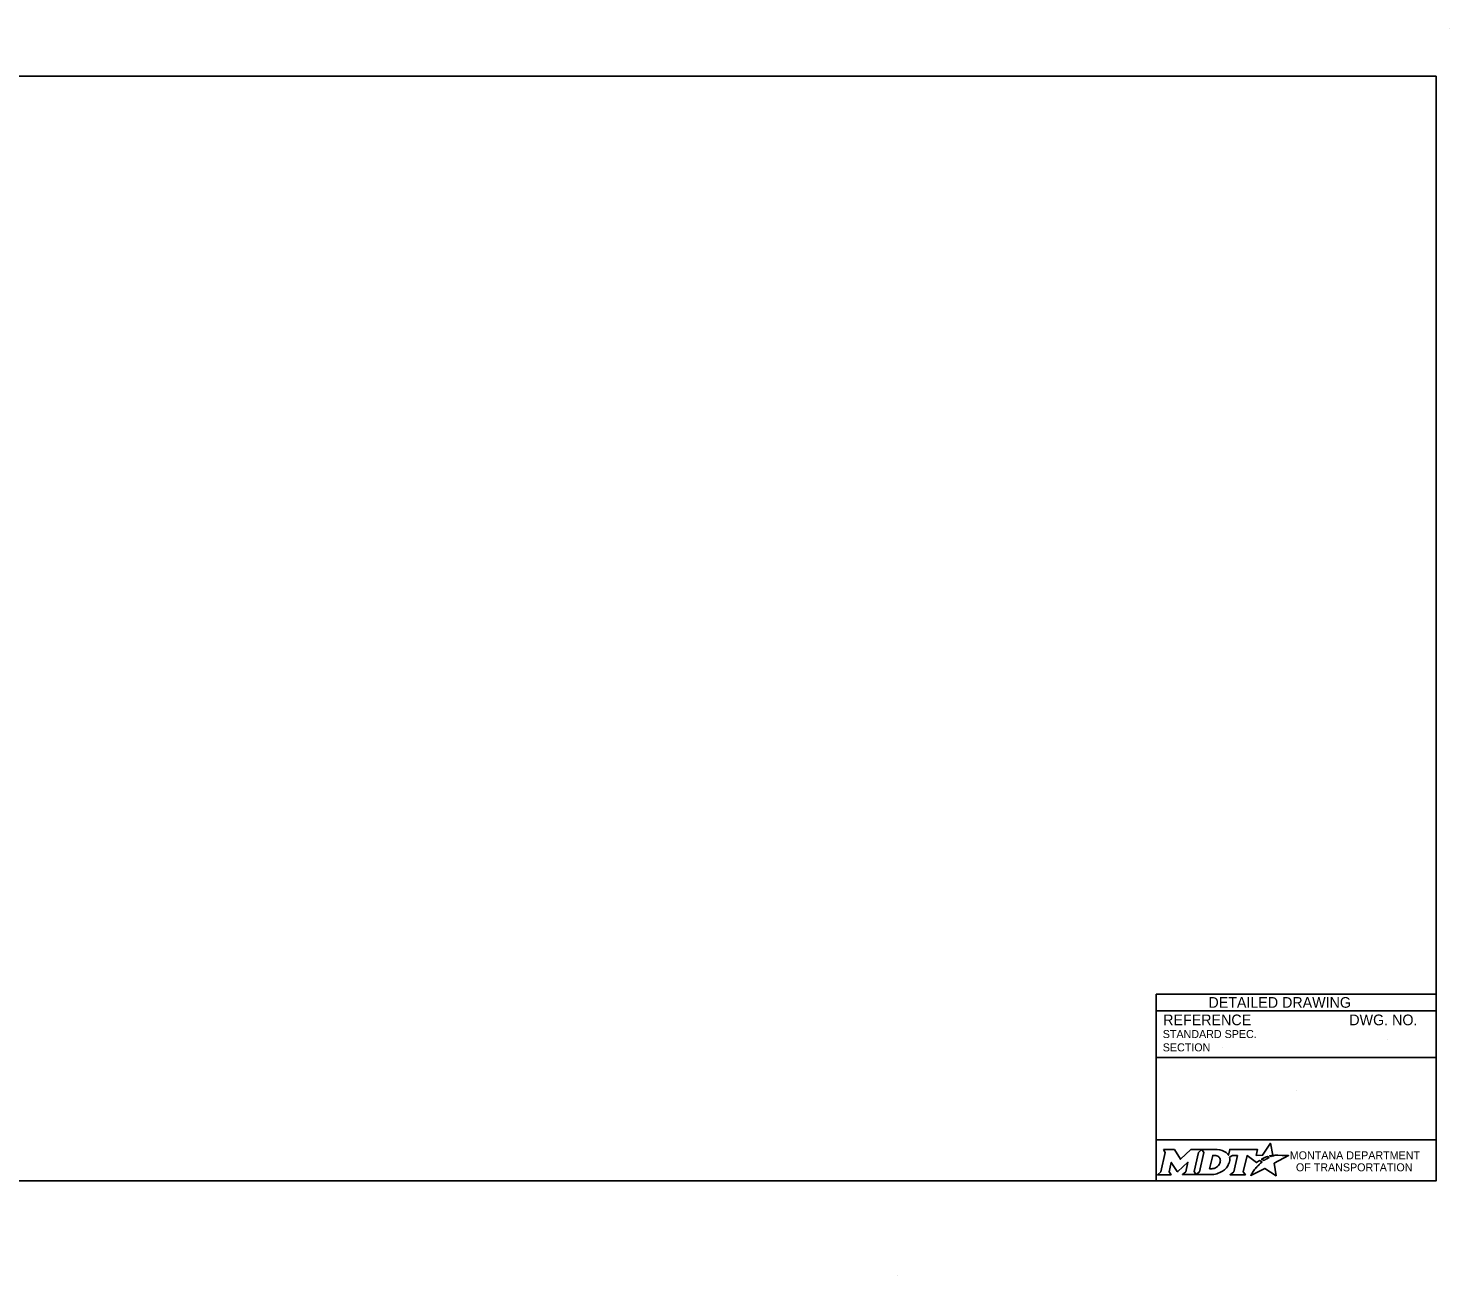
# Model space of a CAD drawing. Extents: x 49991.4 to 50021, y 49987.6 to 50011.4.
# Drawn here: x 50010.39 to 50021.04, y 49999.18 to 50008.52 of the extents above; entities that cross this region are included whole.
import ezdxf

# ---------------------------------------------------------------- set-up
doc = ezdxf.new("R2010")
doc.units = 0
for name, color, linetype in [('Default', 7, 'Continuous'), ('Level 1', 7, 'Continuous'), ('Level 4', 7, 'Continuous')]:
    doc.layers.add(name, color=color, linetype=linetype)

msp = doc.modelspace()

# ---------------------------------------------------------------- linework, layer by layer
at = {"layer": 'Default'}
for points in [[(50019.7, 50000.068), (50019.69, 50000.074), (50019.702, 50000.076), (50019.713, 50000.078), (50019.696, 50000.168), (50019.636, 50000.077), (50019.589, 50000.076), (50019.599, 50000.12), (50019.39, 50000.121), (50019.38, 50000.078), (50019.374, 50000.086)], [(50018.893, 50000.121), (50018.907, 50000.097), (50018.874, 49999.954), (50018.848, 49999.931), (50018.95, 49999.931), (50018.936, 49999.954), (50018.952, 50000.024), (50018.996, 49999.955), (50019.002, 49999.955), (50019.077, 50000.025), (50019.06, 49999.954), (50019.035, 49999.932), (50019.137, 49999.932), (50019.123, 49999.955), (50019.156, 50000.097)], [(50019.156, 50000.097), (50019.182, 50000.121), (50019.099, 50000.121), (50019.02, 50000.048), (50018.975, 50000.12), (50018.893, 50000.121)], [(50019.295, 50000.121), (50019.182, 50000.121), (50019.196, 50000.098), (50019.163, 49999.954), (50019.137, 49999.932), (50019.248, 49999.932)], [(50019.319, 50000.034), (50019.318, 50000.026), (50019.315, 50000.017), (50019.311, 50000.008), (50019.305, 50000.001), (50019.299, 49999.994), (50019.291, 49999.988), (50019.282, 49999.983), (50019.273, 49999.979), (50019.264, 49999.977), (50019.255, 49999.976), (50019.239, 49999.976), (50019.263, 50000.076), (50019.279, 50000.076), (50019.286, 50000.075), (50019.294, 50000.073), (50019.301, 50000.07), (50019.307, 50000.066), (50019.311, 50000.061), (50019.315, 50000.055), (50019.318, 50000.049), (50019.319, 50000.042), (50019.32, 50000.038), (50019.319, 50000.034)], [(50019.387, 50000.062), (50019.411, 50000.075), (50019.448, 50000.075), (50019.42, 49999.954), (50019.392, 49999.931), (50019.508, 49999.931), (50019.491, 49999.954), (50019.52, 50000.075), (50019.591, 50000.023), (50019.612, 50000.038), (50019.632, 50000.027)], [(50019.576, 49999.971), (50019.561, 49999.947), (50019.556, 49999.939), (50019.55, 49999.931), (50019.548, 49999.926), (50019.653, 49999.979), (50019.737, 49999.924), (50019.724, 50000.017), (50019.831, 50000.075), (50019.782, 50000.076), (50019.751, 50000.077), (50019.731, 50000.077), (50019.724, 50000.075), (50019.719, 50000.074), (50019.711, 50000.072), (50019.7, 50000.068)], [(50019.65, 50000.04), (50019.648, 50000.039), (50019.629, 50000.048), (50019.639, 50000.054), (50019.644, 50000.056), (50019.652, 50000.06), (50019.658, 50000.063), (50019.666, 50000.066), (50019.673, 50000.068), (50019.685, 50000.061), (50019.681, 50000.059), (50019.676, 50000.056), (50019.672, 50000.054), (50019.667, 50000.051), (50019.665, 50000.05), (50019.662, 50000.049), (50019.66, 50000.047), (50019.658, 50000.046), (50019.655, 50000.044), (50019.652, 50000.042), (50019.65, 50000.04)], [(50019.293, 49999.939), (50019.302, 49999.942), (50019.315, 49999.947), (50019.335, 49999.958)], [(50019.59, 49999.987), (50019.59, 49999.987)]]:
    msp.add_lwpolyline(points, dxfattribs=at)
for centre, radius, start, end in [((50019.319, 50000.042), 0.0709, 339.5329, 15.8582), ((50019.274, 50000.059), 0.118, 300.9103, 339.1383)]:
    msp.add_arc(centre, radius, start, end, dxfattribs=at)
for centre, major_axis, ratio, start_param, end_param in [((50019.293, 50000.073), (0.0834, -0.0037), 0.568097, 0.61298, 1.570796), ((50019.349, 50000.081), (0.0361, -0.0295), 0.469099, 1.225588, 1.570796), ((50019.583, 49999.979), (-0.00694, -0.00806), 0.008222, 0, 3.137361), ((50019.6, 49999.997), (-0.0098, -0.0102), 0.016458, 3.141593, 6.279097), ((50019.621, 50000.017), (-0.0112, -0.0097), 0.021651, 3.157348, 6.283185), ((50019.248, 50000.08), (0, 0.148), 0.987302, 3.139398, 3.456847)]:
    msp.add_ellipse(centre, major_axis=major_axis, ratio=ratio, start_param=start_param, end_param=end_param, dxfattribs=at)
at = {"layer": 'Level 1'}
for p, q in [((50021.038, 50008.524), (50021.038, 50008.524)), ((50016.9, 49999.176), (50016.9, 49999.176))]:
    msp.add_line(p, q, dxfattribs=at)
msp.add_lwpolyline([(50020.938, 50008.165), (50009.737, 50008.165), (50009.737, 49999.886), (50020.938, 49999.886)], close=True, dxfattribs=at)
at = {"layer": 'Level 4'}
for p, q in [((50020.938, 50001.286), (50018.838, 50001.286)), ((50018.838, 50001.286), (50018.838, 49999.886)), ((50020.938, 50001.161), (50018.838, 50001.161)), ((50020.574, 50000.946), (50020.574, 50000.946)), ((50020.938, 50000.811), (50018.838, 50000.811)), ((50019.332, 50000.886), (50019.332, 50000.886)), ((50019.888, 50000.562), (50019.888, 50000.562)), ((50020.938, 50000.193), (50018.838, 50000.193))]:
    msp.add_line(p, q, dxfattribs=at)

# ---------------------------------------------------------------- texts
at = {"layer": 'Default'}
for s, p in [('MONTANA DEPARTMENT', (50019.84, 50000.047)), ('OF TRANSPORTATION', (50019.886, 49999.957))]:
    msp.add_text(s, height=0.06, rotation=360, dxfattribs=at).set_placement(p)
at = {"layer": 'Level 4'}
for s, height, p in [('DETAILED DRAWING', 0.0799, (50019.23, 50001.183)), ('REFERENCE', 0.08, (50018.891, 50001.052)), ('DWG. NO.', 0.08, (50020.286, 50001.052)), ('STANDARD SPEC.', 0.06, (50018.888, 50000.956)), ('SECTION', 0.06, (50018.888, 50000.856))]:
    msp.add_text(s, height=height, dxfattribs=at).set_placement(p)

doc.saveas('drawing.dxf')
